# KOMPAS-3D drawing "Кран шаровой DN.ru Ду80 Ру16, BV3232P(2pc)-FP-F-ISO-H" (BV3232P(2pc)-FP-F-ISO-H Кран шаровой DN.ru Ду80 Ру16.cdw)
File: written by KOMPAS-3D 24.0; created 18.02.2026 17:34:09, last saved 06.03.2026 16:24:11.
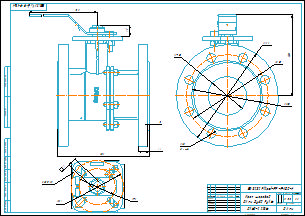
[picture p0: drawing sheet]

Document properties: Автор: R2D2; Форматы листов документа: A2; Полное имя файла: BV3232P(2pc)-FP-F-ISO-H Кран шаровой DN.ru Ду80 Ру16.m3d; Масса: 12.93; Наименование: Кран шаровой DN.ru Ду80 Ру16; Количество листов документа: 1; Примечание: D160-22136

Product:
- Component [detail]: Сборка  | qty 1  | pos. 1  | source file: исходные материалы\1.m3d
- Component [detail]: Сборка  | qty 1  | pos. 1  | Масса: 0.498058; source file: исходные материалы\2.m3d
- Part/product: Кран шаровой DN.ru Ду80 Ру16  | designation BV3232P(2pc)-FP-F-ISO-H
    Масса: 12.93
    Раздел спецификации: Прочие изделия
    Примечание: D160-22136

Views: Вид 1, Справа, Проекционный вид 2
Referenced files in E:\Работа\Зайцев\BV3232P(2pc)-FP-F-ISO-H Кран шаровой DN.ru Ду15-300 Ру16-40\DN80 PN16\: BV3232P(2pc)-FP-F-ISO-H Кран шаровой DN.ru Ду80 Ру16.m3d
Referenced files in E:\Работа\Зайцев\Для компаса\: чертеж DN.ru А3.cdt
Referenced files in E:\Работа\Зайцев\BV3232P(2pc)-FP-F-ISO-H Кран шаровой DN.ru Ду15-300 Ру16-40\DN80 PN16\исходные материалы\: 1.m3d, Деталь1 Деталь1.m3d, Деталь2 Деталь2.m3d, Деталь3 Деталь3.m3d, Деталь6 Деталь6.m3d, Деталь5 Деталь5.m3d, Деталь7 Деталь7.m3d, AS 1421 - M8 x 30 засверленный конец AS 1421 - M8 x 30 засверленный конец.m3d, AS 1420 - 1973 - M10 x 30 AS 1420 - 1973 - M10 x 30.m3d, ANSI B18.2.4.2M - M10x1,5 ANSI B18.2.4.2M - M10x1,5 - 16.m3d, ANSI B18.2.4.2M - M8x1,25 ANSI B18.2.4.2M - M8x1,25 - 13.m3d, BS 3692 - M12 BS 3692 - M12(4).m3d, 2.m3d
Referenced files in C:\Program Files\ASCON\KOMPAS-3D v24\Libs\PolynomLib\DATA\vault\Methods\Kompas\3D\: PLib_Nut_OST92_900.m3d
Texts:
  BV3232P(2pc)-FP-F-ISO-H
  чертеж DN.ru А3.cdt
  Кран шаровой
  DN.ru Ду80 Ру16
  Твердое тело1
  Деталь1
  Деталь1 Деталь1
  Деталь2
  Деталь2 Деталь2
  Деталь3
  Деталь3 Деталь3
  Деталь6
  Деталь6 Деталь6
  Деталь5
  Деталь5 Деталь5
  Деталь7
  Деталь7 Деталь7
  Solid1
  AS 1421 - M8 x 30 засверленный конец
  AS 1421 - M8 x 30 засверленный   конец
  AS 1421 - M8 x 30 засверленный   конец AS 1421 - M8 x 30 засверленный конец
  AS 1420 - 1973 - M10 x 30
  AS 1420 - 1973 - M10 x 30 AS 1420 - 1973 - M10 x 30
  ANSI B18.2.4.2M - M10x1,5 - 16
  ANSI B18.2.4.2M - M10x1,5
  ANSI B18.2.4.2M - M10x1,5 ANSI B18.2.4.2M - M10x1,5 - 16
  ANSI B18.2.4.2M - M8x1,25 - 13
  ANSI B18.2.4.2M - M8x1,25
  ANSI B18.2.4.2M - M8x1,25 ANSI B18.2.4.2M - M8x1,25 - 13
  BS 3692 - M12(4)
  BS 3692 - M12
  BS 3692 - M12 BS 3692 - M12(4)
  Сборка
  Сборка Сборка
  Гайка М20-6H ГОСТ 5916-70
  Кран шаровой DN.ru Ду80 Ру16
  BV3232P(2pc)-FP-F-ISO-H Кран шаровой DN.ru Ду80 Ру16
Dimensions and other numbers on the sheet: 0; 3; 2; 4; 321; 21; 180; 22; 200; 160; 138; 18; 8 отв.; 76; 158; 1:1; 1; 12,93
